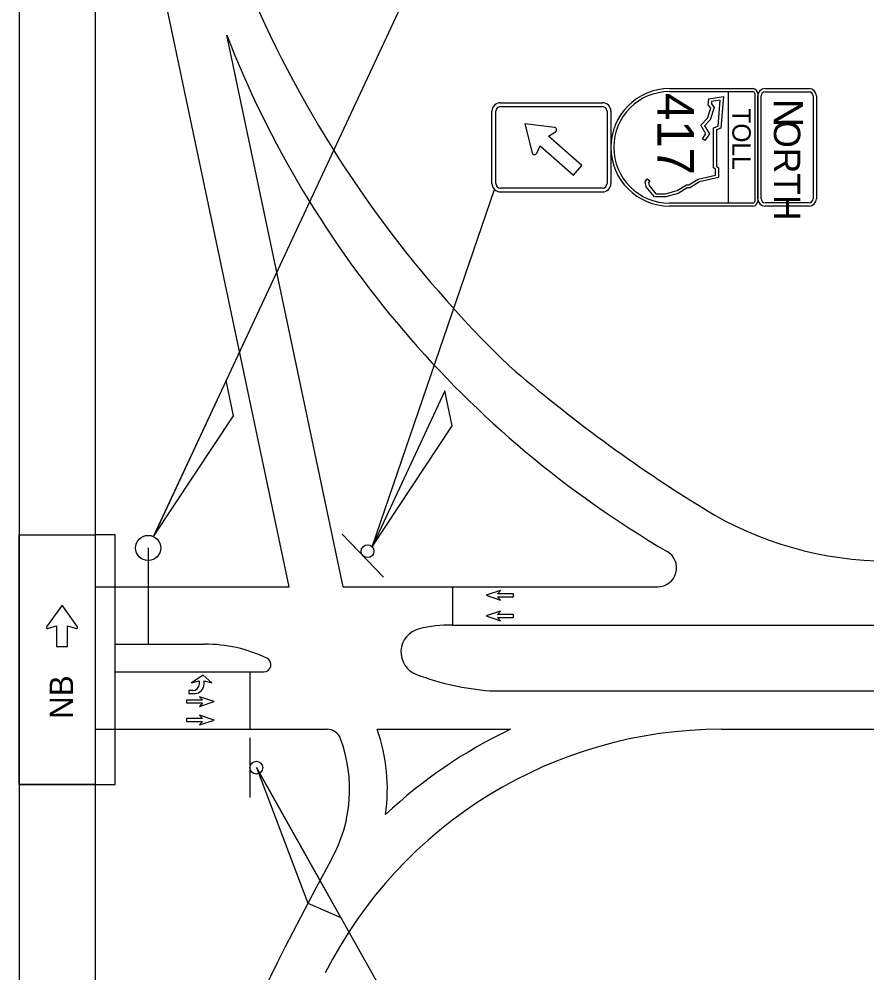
# Model space of a CAD drawing. Extents: x -830008.4 to -829992.7, y 1290284.1 to 1290294.4.
# Drawn here: x -830000.072 to -829997.148, y 1290288.685 to 1290291.974 of the extents above; entities that cross this region are included whole.
import ezdxf

# ---------------------------------------------------------------- set-up
doc = ezdxf.new("R2010")
doc.units = 0
for name, color, linetype in [('1', 7, 'Continuous'), ('DirArrowsPavt', 7, 'Continuous'), ('OOCEA Logo', 7, 'Continuous'), ('PlotBorder_dp', 7, 'Continuous'), ('SheetBorder_dp', 7, 'Continuous'), ('SignPanel', 7, 'Continuous')]:
    doc.layers.add(name, color=color, linetype=linetype)

msp = doc.modelspace()

# ---------------------------------------------------------------- linework, layer by layer
at = {"layer": '1'}
for p, q in [((-830000.0719, 1290294.228), (-830000.0719, 1290285.328)), ((-829999.8091, 1290294.0613), (-829999.8091, 1290288.9868)), ((-829999.1404, 1290290.0166), (-829999.6786, 1290292.5639)), ((-829999.6084, 1290290.1898), (-829998.5302, 1290292.5004)), ((-829998.9542, 1290290.0166), (-829999.356, 1290291.9188)), ((-829998.8545, 1290290.1545), (-829998.433, 1290291.3867)), ((-830000.0719, 1290290.196), (-829999.8091, 1290290.196)), ((-829999.8091, 1290290.0166), (-829999.1404, 1290290.0166)), ((-829998.9542, 1290290.0166), (-829997.8698, 1290290.0166)), ((-829998.578, 1290290.0166), (-829998.578, 1290289.8838)), ((-829998.578, 1290289.8838), (-829993.659, 1290289.8838)), ((-829999.7401, 1290289.8188), (-829999.4321, 1290289.8188)), ((-829999.7401, 1290289.7229), (-829999.2285, 1290289.7229)), ((-829999.2763, 1290289.7229), (-829999.2763, 1290289.5251)), ((-829998.4483, 1290289.6579), (-829992.7742, 1290289.6579)), ((-829999.8091, 1290289.5251), (-829999.0101, 1290289.5251)), ((-829998.8368, 1290289.5251), (-829998.3772, 1290289.5251)), ((-829997.6499, 1290289.5251), (-829992.7742, 1290289.5251)), ((-829999.2537, 1290289.3928), (-829998.4458, 1290287.9567)), ((-830000.0719, 1290289.3342), (-829999.8091, 1290289.3342)), ((-829999.8091, 1290288.9868), (-829999.8096, 1290286.9607))]:
    msp.add_line(p, q, dxfattribs=at)
msp.add_lwpolyline([(-829999.8091, 1290289.3342), (-830000.0719, 1290289.3342), (-830000.0719, 1290290.196), (-829999.8091, 1290290.196)], close=True, dxfattribs=at)
msp.add_lwpolyline([(-829999.7401, 1290290.196), (-829999.8091, 1290290.196), (-829999.8091, 1290289.3342), (-829999.7401, 1290289.3342), (-829999.7401, 1290290.196)], dxfattribs=at)
for centre, radius, start, end in [((-829995.6233, 1290293.6404), 3.9753, 185.3062, 226.0707), ((-829996.0337, 1290293.2144), 3.566, 201.3035, 239.6251), ((-829994.9707, 1290294.727), 5.2183, 229.1883, 238.3217), ((-829997.0749, 1290291.317), 1.2114, 238.3217, 270), ((-829997.8698, 1290290.0817), 0.0651, 270, 59.6251), ((-829998.5928, 1290289.4737), 0.4104, 87.9263, 104.0818), ((-829998.6725, 1290289.7915), 0.0827, 104.0818, 249.5385), ((-829999.4321, 1290289.3188), 0.5, 64.6242, 90), ((-829999.2285, 1290289.7479), 0.025, 270, 64.6242), ((-829998.3749, 1290290.589), 0.934, 249.5341, 265.495), ((-829997.6499, 1290287.9944), 1.5306, 90, 153.1865), ((-829999.0101, 1290289.4751), 0.05, 20.3256, 90), ((-829999.4321, 1290289.3188), 0.63, 352.0355, 19.1156), ((-829997.6499, 1290287.9944), 1.6947, 115.4166, 133.117), ((-829999.4321, 1290289.3188), 0.5, 331.1587, 20.3256), ((-829990.0742, 1290284.1655), 10.183, 151.15873, 161.43615)]:
    msp.add_arc(centre, radius, start, end, dxfattribs=at)
at = {"layer": 'DirArrowsPavt'}
for p, q in [((-829998.4117, 1290290.004), (-829998.4617, 1290289.9873)), ((-829998.4617, 1290289.9873), (-829998.4117, 1290289.9707)), ((-829998.4217, 1290289.9923), (-829998.4117, 1290290.004)), ((-829998.3667, 1290289.9923), (-829998.4217, 1290289.9923)), ((-829998.4117, 1290289.9707), (-829998.4217, 1290289.9823)), ((-829998.4217, 1290289.9823), (-829998.3667, 1290289.9823)), ((-829998.3667, 1290289.9823), (-829998.3667, 1290289.9923)), ((-829998.4117, 1290289.9325), (-829998.4617, 1290289.9159)), ((-829998.4617, 1290289.9159), (-829998.4117, 1290289.8992)), ((-829998.4217, 1290289.9209), (-829998.4117, 1290289.9325)), ((-829998.3667, 1290289.9209), (-829998.4217, 1290289.9209)), ((-829998.3667, 1290289.9109), (-829998.3667, 1290289.9209)), ((-829998.4117, 1290289.8992), (-829998.4217, 1290289.9109)), ((-829998.4217, 1290289.9109), (-829998.3667, 1290289.9109)), ((-829999.4733, 1290289.6587), (-829999.487, 1290289.6587)), ((-829999.4395, 1290289.6258), (-829999.4945, 1290289.6258)), ((-829999.4945, 1290289.6258), (-829999.4945, 1290289.6158)), ((-829999.3995, 1290289.6208), (-829999.4495, 1290289.6374)), ((-829999.4495, 1290289.6374), (-829999.4395, 1290289.6258)), ((-829999.4495, 1290289.6041), (-829999.3995, 1290289.6208)), ((-829999.4945, 1290289.6158), (-829999.4395, 1290289.6158)), ((-829999.4395, 1290289.6158), (-829999.4495, 1290289.6041)), ((-829999.4395, 1290289.5619), (-829999.4945, 1290289.5619)), ((-829999.4945, 1290289.5619), (-829999.4945, 1290289.5519)), ((-829999.3995, 1290289.5569), (-829999.4495, 1290289.5736)), ((-829999.4495, 1290289.5736), (-829999.4395, 1290289.5619)), ((-829999.4495, 1290289.5402), (-829999.3995, 1290289.5569)), ((-829999.4945, 1290289.5519), (-829999.4395, 1290289.5519)), ((-829999.4395, 1290289.5519), (-829999.4495, 1290289.5402))]:
    msp.add_line(p, q, dxfattribs=at)
for points in [[(-829999.4337, 1290289.6815), (-829999.4337, 1290289.6921), (-829999.407, 1290289.6854), (-829999.437, 1290289.7121), (-829999.477, 1290289.6854), (-829999.4504, 1290289.6921), (-829999.4504, 1290289.6817)], [(-829999.487, 1290289.6587), (-829999.487, 1290289.6487), (-829999.4665, 1290289.6487)]]:
    msp.add_lwpolyline(points, dxfattribs=at)
for centre, radius in [((-829999.4733, 1290289.6817), 0.023), ((-829999.4665, 1290289.6815), 0.0328)]:
    msp.add_arc(centre, radius, 270, 0, dxfattribs=at)
at = {"layer": 'OOCEA Logo'}
msp.add_line((-829999.6267, 1290290.1505), (-829999.6267, 1290289.8188), dxfattribs=at)
msp.add_circle((-829999.6267, 1290290.1505), 0.0434, dxfattribs=at)
msp.add_circle((-829999.6267, 1290290.1505), 0.0434, dxfattribs=at)
at = {"layer": 'PlotBorder_dp'}
for p, q in [((-829998.9574, 1290290.1985), (-829998.8154, 1290290.0495)), ((-829999.2758, 1290289.4957), (-829999.2758, 1290289.2899))]:
    msp.add_line(p, q, dxfattribs=at)
for centre in [(-829998.8704, 1290290.1392), (-829999.2537, 1290289.3928)]:
    msp.add_circle(centre, 0.0221, dxfattribs=at)
at = {"layer": 'SheetBorder_dp'}
for p, q in [((-829997.6958, 1290291.6787), (-829997.6933, 1290291.6996)), ((-829997.6933, 1290291.6996), (-829997.6432, 1290291.7074)), ((-829997.6548, 1290291.6949), (-829997.6838, 1290291.6904)), ((-829997.6617, 1290291.6055), (-829997.6548, 1290291.6949)), ((-829997.6432, 1290291.7074), (-829997.6517, 1290291.598)), ((-829997.6981, 1290291.6326), (-829997.6868, 1290291.6672)), ((-829997.6868, 1290291.6672), (-829997.6958, 1290291.6787)), ((-829997.6751, 1290291.6693), (-829997.6888, 1290291.6271)), ((-829997.6838, 1290291.6904), (-829997.6848, 1290291.6818)), ((-829997.6848, 1290291.6818), (-829997.6751, 1290291.6693)), ((-829997.721, 1290291.6079), (-829997.6981, 1290291.6326)), ((-829997.6888, 1290291.6271), (-829997.708, 1290291.6064)), ((-829998.2261, 1290291.6009), (-829998.3284, 1290291.613)), ((-829998.3284, 1290291.613), (-829998.3031, 1290291.5132)), ((-829997.7039, 1290291.5788), (-829997.721, 1290291.6079)), ((-829997.708, 1290291.6064), (-829997.6915, 1290291.5784)), ((-829997.6779, 1290291.5991), (-829997.6617, 1290291.6055)), ((-829997.6779, 1290291.4609), (-829997.6779, 1290291.5991)), ((-829997.6517, 1290291.598), (-829997.6674, 1290291.5919)), ((-829998.2459, 1290291.5705), (-829998.2226, 1290291.5851)), ((-829998.1309, 1290291.4696), (-829998.2459, 1290291.5705)), ((-829997.7157, 1290291.5614), (-829997.7039, 1290291.5788)), ((-829997.7069, 1290291.5555), (-829997.7157, 1290291.5614)), ((-829997.6915, 1290291.5784), (-829997.7069, 1290291.5555)), ((-829997.6674, 1290291.5919), (-829997.6674, 1290291.4665)), ((-829998.287, 1290291.5117), (-829998.2755, 1290291.5368)), ((-829998.2755, 1290291.5368), (-829998.1605, 1290291.4358)), ((-829998.1605, 1290291.4358), (-829998.1309, 1290291.4696)), ((-829997.671, 1290291.4562), (-829997.6779, 1290291.4609)), ((-829997.6674, 1290291.4665), (-829997.6604, 1290291.4618)), ((-829997.6604, 1290291.4618), (-829997.6604, 1290291.428)), ((-829997.7302, 1290291.4226), (-829997.671, 1290291.4364)), ((-829997.6604, 1290291.428), (-829997.7262, 1290291.4127)), ((-829997.671, 1290291.4364), (-829997.671, 1290291.4562)), ((-829997.9132, 1290291.4125), (-829997.906, 1290291.4229)), ((-829997.9093, 1290291.3961), (-829997.9132, 1290291.4125)), ((-829997.881, 1290291.3615), (-829997.9093, 1290291.3961)), ((-829997.906, 1290291.4229), (-829997.8973, 1290291.4169)), ((-829997.8973, 1290291.4169), (-829997.9019, 1290291.4104)), ((-829997.9019, 1290291.4104), (-829997.8996, 1290291.4009)), ((-829997.8996, 1290291.4009), (-829997.876, 1290291.3721)), ((-829997.8032, 1290291.3829), (-829997.771, 1290291.4025)), ((-829997.771, 1290291.4025), (-829997.7626, 1290291.4025)), ((-829997.7626, 1290291.4025), (-829997.7302, 1290291.4226)), ((-829997.7262, 1290291.4127), (-829997.7596, 1290291.3919)), ((-829997.876, 1290291.3721), (-829997.8428, 1290291.3721)), ((-829997.8428, 1290291.3721), (-829997.8032, 1290291.3829)), ((-829997.799, 1290291.3731), (-829997.8414, 1290291.3615)), ((-829997.768, 1290291.3919), (-829997.799, 1290291.3731)), ((-829997.7596, 1290291.3919), (-829997.768, 1290291.3919)), ((-829997.8414, 1290291.3615), (-829997.881, 1290291.3615)), ((-829999.9239, 1290289.9526), (-829999.977, 1290289.8779)), ((-829999.8708, 1290289.8779), (-829999.8708, 1290289.8779))]:
    msp.add_line(p, q, dxfattribs=at)
for points in [[(-829997.8289, 1290291.7344), (-829997.542, 1290291.7344)], [(-829997.8289, 1290291.7243), (-829997.542, 1290291.7243)], [(-829997.6264, 1290291.7243), (-829997.6264, 1290291.3395)], [(-829997.4998, 1290291.7344), (-829997.3479, 1290291.7344)], [(-829997.5352, 1290291.7175), (-829997.5352, 1290291.3463)], [(-829997.5251, 1290291.7175), (-829997.5251, 1290291.3463)], [(-829997.5251, 1290291.3547), (-829997.5251, 1290291.7091)], [(-829997.5135, 1290291.3547), (-829997.5135, 1290291.7091)], [(-829997.4998, 1290291.7228), (-829997.3479, 1290291.7228)], [(-829997.3342, 1290291.7091), (-829997.3342, 1290291.3547)], [(-829997.3226, 1290291.7091), (-829997.3226, 1290291.3547)], [(-829998.4122, 1290291.6857), (-829998.0605, 1290291.6857)], [(-829998.4122, 1290291.6723), (-829998.0605, 1290291.6723)], [(-829998.4415, 1290291.4073), (-829998.4415, 1290291.6564)], [(-829998.4281, 1290291.4073), (-829998.4281, 1290291.6564)], [(-829998.0446, 1290291.6564), (-829998.0446, 1290291.4073)], [(-829998.0312, 1290291.6564), (-829998.0312, 1290291.4073)], [(-829998.0605, 1290291.3914), (-829998.4122, 1290291.3914)], [(-829998.0605, 1290291.3779), (-829998.4122, 1290291.3779)], [(-829997.542, 1290291.3395), (-829997.8289, 1290291.3395)], [(-829997.542, 1290291.3294), (-829997.8289, 1290291.3294)], [(-829997.3479, 1290291.341), (-829997.4998, 1290291.341)], [(-829997.3479, 1290291.3294), (-829997.4998, 1290291.3294)], [(-829999.8708, 1290289.8779), (-829999.9239, 1290289.9526), (-829999.9239, 1290289.9526)], [(-829999.9735, 1290289.8721), (-829999.9425, 1290289.8814), (-829999.9425, 1290289.8102), (-829999.9052, 1290289.8102), (-829999.9052, 1290289.8814), (-829999.8743, 1290289.8721)]]:
    msp.add_lwpolyline(points, dxfattribs=at)
for centre, radius, start, end in [((-829997.8289, 1290291.5319), 0.2025, 90, 270), ((-829997.8289, 1290291.5319), 0.1924, 90, 270), ((-829997.542, 1290291.7175), 0.0169, 0, 90), ((-829997.542, 1290291.7175), 0.00675, 0, 90), ((-829997.4998, 1290291.7091), 0.0253, 90, 180), ((-829997.3479, 1290291.7091), 0.0253, 0, 90), ((-829997.4998, 1290291.7091), 0.0137, 90, 180), ((-829997.3479, 1290291.7091), 0.0137, 0, 90), ((-829998.4122, 1290291.6564), 0.0293, 90, 180), ((-829998.4122, 1290291.6564), 0.0159, 90, 179.9456), ((-829998.0605, 1290291.6564), 0.0293, 0, 90), ((-829998.0605, 1290291.6564), 0.0159, 0.0544, 90), ((-829998.2271, 1290291.5924), 0.00855, 302.0987, 83.2311), ((-829998.2948, 1290291.5153), 0.00855, 194.2549, 335.3873), ((-829998.4122, 1290291.4073), 0.0293, 180, 270), ((-829998.4122, 1290291.4073), 0.0159, 180, 270), ((-829998.0605, 1290291.4073), 0.0159, 270, 0), ((-829998.0605, 1290291.4073), 0.0293, 270, 0), ((-829997.542, 1290291.3463), 0.0169, 270, 0), ((-829997.542, 1290291.3463), 0.00675, 270, 0), ((-829997.4998, 1290291.3547), 0.0253, 180, 270), ((-829997.4998, 1290291.3547), 0.0137, 180, 270), ((-829997.3479, 1290291.3547), 0.0253, 270, 0), ((-829997.3479, 1290291.3547), 0.0137, 270, 0), ((-829999.9741, 1290289.8755), 0.00355, 144.6076, 287.1805), ((-829999.8736, 1290289.8755), 0.00355, 252.8195, 35.3924)]:
    msp.add_arc(centre, radius, start, end, dxfattribs=at)
at = {"layer": 'SignPanel'}
for p, q in [((-829999.3574, 1290290.7275), (-829999.6084, 1290290.1898)), ((-829999.3321, 1290290.6066), (-829999.3574, 1290290.7275)), ((-829998.6035, 1290290.6922), (-829998.8545, 1290290.1545)), ((-829998.5782, 1290290.5712), (-829998.6035, 1290290.6922)), ((-829999.6084, 1290290.1898), (-829999.3321, 1290290.6066)), ((-829998.8545, 1290290.1545), (-829998.5782, 1290290.5712)), ((-829999.2537, 1290289.3928), (-829999.0759, 1290288.9255)), ((-829998.9628, 1290288.8756), (-829999.2537, 1290289.3928)), ((-829999.0759, 1290288.9255), (-829998.9628, 1290288.8756))]:
    msp.add_line(p, q, dxfattribs=at)

# ---------------------------------------------------------------- texts
at = {"layer": '1'}
msp.add_text('NB', height=0.081, rotation=90, dxfattribs=at).set_placement((-829999.8857, 1290289.5607))
at = {"layer": 'SheetBorder_dp'}
for s, height, p in [('417', 0.12656, (-829997.8711, 1290291.7193)), ('TOLL', 0.06328, (-829997.6124, 1290291.6663)), ('N', 0.1013, (-829997.4704, 1290291.6989)), ('ORTH', 0.09113, (-829997.4693, 1290291.625))]:
    msp.add_text(s, height=height, rotation=270, dxfattribs=at).set_placement(p)

doc.saveas('drawing.dxf')
